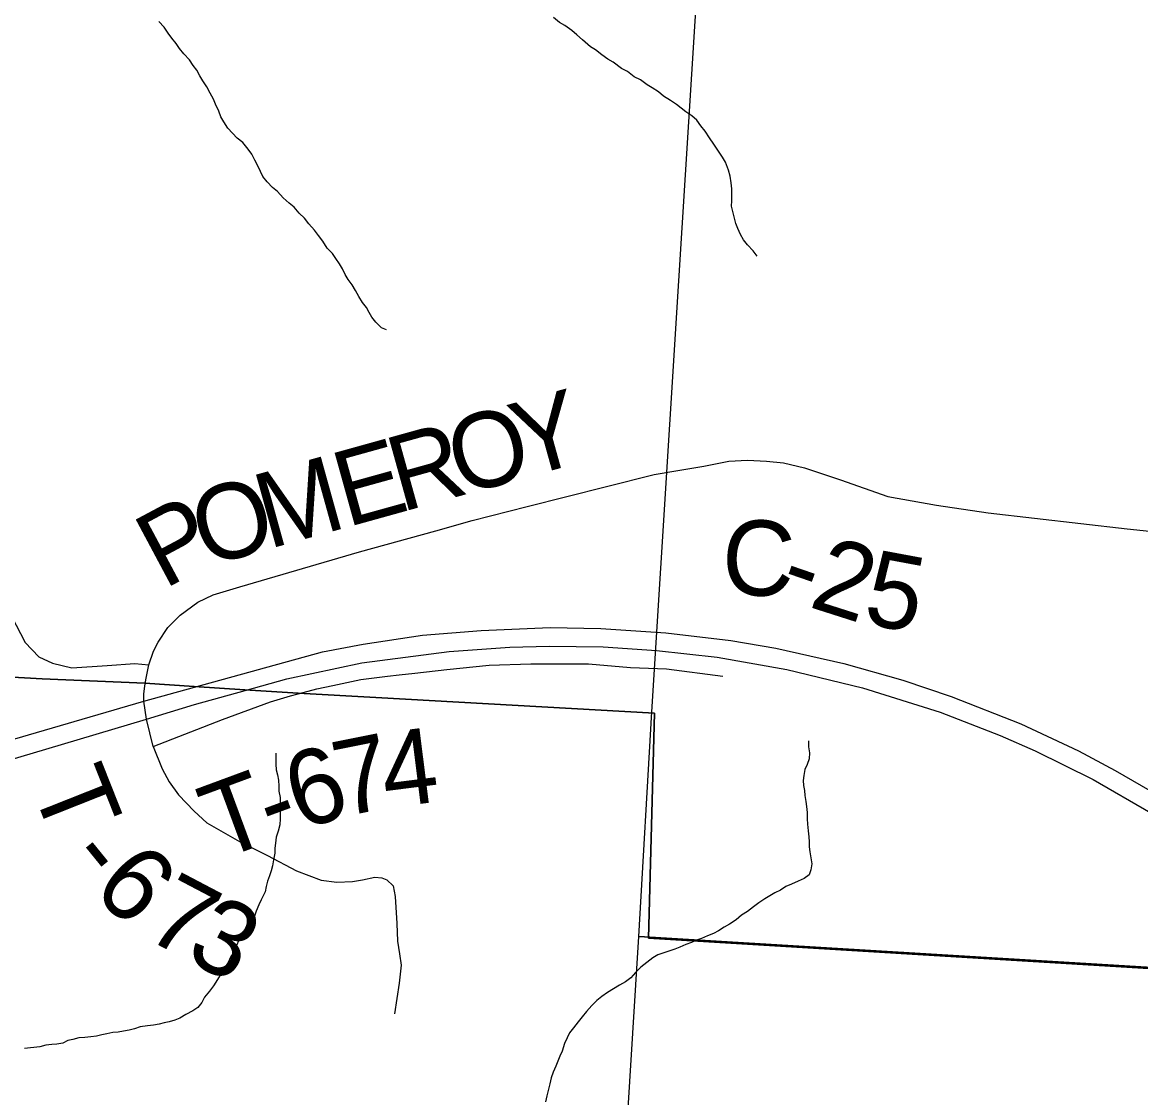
# Model space of a CAD drawing. Extents: x -20.2 to 34, y 0 to 22.
# Drawn here: x 6.324 to 7.17, y 15.823 to 16.636 of the extents above; entities that cross this region are included whole.
import ezdxf

# ---------------------------------------------------------------- set-up
doc = ezdxf.new("R2010")
doc.units = 0
for name, color, linetype in [('Default', 7, 'Continuous'), ('GM_X_County_Road', 7, 'Continuous'), ('GM_X_County_Road_Text', 7, 'Continuous'), ('GM_X_Minor_River', 7, 'Continuous'), ('GM_X_Section', 7, 'Continuous'), ('GM_X_State_Route', 7, 'Continuous'), ('GM_X_Township_Road', 7, 'Continuous'), ('GM_X_Township_Road_Text', 7, 'Continuous'), ('GM_X_US_Route', 7, 'Continuous')]:
    doc.layers.add(name, color=color, linetype=linetype)

msp = doc.modelspace()

# ---------------------------------------------------------------- linework, layer by layer
at = {"layer": 'Default'}
for points in [[(7.35857, 15.90937), (6.79759, 15.94346), (6.80213, 16.11334), (6.59162, 16.12522), (6.53272, 16.12856), (6.49252, 16.13112), (6.45426, 16.13368), (6.41689, 16.13622), (6.33933, 16.13945), (5.77707, 16.17118)], [(5.77707, 16.17118), (6.33933, 16.13945), (6.41689, 16.13622), (6.45426, 16.13368), (6.49252, 16.13112), (6.53272, 16.12856), (6.59162, 16.12522), (6.80213, 16.11334), (6.79759, 15.94346), (7.35857, 15.90937)]]:
    msp.add_lwpolyline(points, dxfattribs=at)
at = {"layer": 'GM_X_County_Road'}
for points in [[(6.63691, 16.25133), (6.66435, 16.25899), (6.70605, 16.26963), (6.76584, 16.28474), (6.80196, 16.29397), (6.81836, 16.2967), (6.83948, 16.30018), (6.85837, 16.30391), (6.87253, 16.30466), (6.88695, 16.30391), (6.89967, 16.30262), (6.91553, 16.29894), (6.94286, 16.28974), (6.97865, 16.27732), (7.01542, 16.27061), (7.05444, 16.26489), (7.15949, 16.25286), (7.23635, 16.24476)], [(6.41615, 16.12258), (6.41621, 16.12812), (6.41677, 16.13388), (6.4171, 16.13569), (6.41789, 16.13993), (6.41989, 16.15005), (6.4235, 16.16027), (6.42697, 16.16705), (6.43436, 16.17814), (6.4435, 16.1875), (6.45697, 16.19725), (6.46861, 16.20282), (6.48882, 16.20899), (6.5793, 16.23532), (6.63691, 16.25133)], [(6.42329, 16.08835), (6.41816, 16.10902), (6.41615, 16.12258)]]:
    msp.add_lwpolyline(points, dxfattribs=at)
at = {"layer": 'GM_X_Minor_River'}
for points in [[(6.87983, 16.45884), (6.87674, 16.46298), (6.87252, 16.46748), (6.86944, 16.47124), (6.86711, 16.47539), (6.86516, 16.47992), (6.8636, 16.4837), (6.86279, 16.48749), (6.86161, 16.49165), (6.86041, 16.49657), (6.86074, 16.50075), (6.86069, 16.50531), (6.86064, 16.50987), (6.8602, 16.51442), (6.85939, 16.51934), (6.8582, 16.52389), (6.85585, 16.52993), (6.85353, 16.5337), (6.85005, 16.53898), (6.84696, 16.5435), (6.84386, 16.54839), (6.84039, 16.55329), (6.83731, 16.55743), (6.83422, 16.56157), (6.83039, 16.56493), (6.8258, 16.56792), (6.8189, 16.57353), (6.81431, 16.57651), (6.80896, 16.57986), (6.80512, 16.58323), (6.80053, 16.58621), (6.79671, 16.58844), (6.79173, 16.59217), (6.78677, 16.59439), (6.78179, 16.59851), (6.77721, 16.60073), (6.77107, 16.60559), (6.76687, 16.60781), (6.76228, 16.61117), (6.75768, 16.61491), (6.75386, 16.61714), (6.74772, 16.62239), (6.74351, 16.62613), (6.73967, 16.6295), (6.73431, 16.63323), (6.73049, 16.63546), (6.72589, 16.6392)], [(6.59958, 16.40329), (6.59576, 16.40476), (6.59154, 16.40889), (6.58846, 16.41265), (6.58652, 16.41642), (6.58458, 16.42019), (6.58149, 16.42395), (6.57879, 16.42848), (6.57608, 16.433), (6.57375, 16.43715), (6.57067, 16.44129), (6.56834, 16.44506), (6.5664, 16.44921), (6.56408, 16.45298), (6.56137, 16.45712), (6.55867, 16.46089), (6.55482, 16.46501), (6.55135, 16.47029), (6.54826, 16.47443), (6.54518, 16.47856), (6.54095, 16.48345), (6.53748, 16.48758), (6.53364, 16.49133), (6.52979, 16.49584), (6.52596, 16.49883), (6.52136, 16.50295), (6.51713, 16.50784), (6.5133, 16.51082), (6.50945, 16.51495), (6.50599, 16.51909), (6.50443, 16.52287), (6.50248, 16.52664), (6.50015, 16.53155), (6.49782, 16.53607), (6.49512, 16.53984), (6.49089, 16.54472), (6.48667, 16.54809), (6.48321, 16.55184), (6.47975, 16.5556), (6.47666, 16.5605), (6.47434, 16.56426), (6.47277, 16.56842), (6.47043, 16.57371), (6.46887, 16.57749), (6.46616, 16.58201), (6.46382, 16.58692), (6.46073, 16.59144), (6.45841, 16.59521), (6.45609, 16.59936), (6.45338, 16.60312), (6.45068, 16.60726), (6.44645, 16.61177), (6.44299, 16.6159), (6.44066, 16.61967), (6.4372, 16.6238), (6.4345, 16.62757), (6.43141, 16.63209), (6.42757, 16.63622)], [(6.91864, 16.09255), (6.91867, 16.08799), (6.91946, 16.08344), (6.91912, 16.07888), (6.91763, 16.07469), (6.91576, 16.07088), (6.91503, 16.06632), (6.91468, 16.06252), (6.91471, 16.05872), (6.91549, 16.05493), (6.9159, 16.05114), (6.91669, 16.04658), (6.9171, 16.04279), (6.91751, 16.03824), (6.91755, 16.03368), (6.91796, 16.0295), (6.91837, 16.02457), (6.91879, 16.02002), (6.91919, 16.01622), (6.91922, 16.01243), (6.91963, 16.00863), (6.92042, 16.00408), (6.92121, 15.99953), (6.92049, 15.99496), (6.919, 15.99116), (6.91522, 15.98847), (6.91068, 15.98654), (6.90576, 15.98423), (6.9016, 15.9823), (6.89744, 15.97961), (6.89327, 15.97768), (6.88949, 15.97537), (6.88571, 15.97307), (6.88118, 15.97), (6.87703, 15.96693), (6.87249, 15.96348), (6.86796, 15.96079), (6.86381, 15.95734), (6.85889, 15.95389), (6.85474, 15.95158), (6.85058, 15.94889), (6.84679, 15.94697), (6.84225, 15.94504), (6.83771, 15.94311), (6.83392, 15.94194), (6.83014, 15.94001), (6.82597, 15.93846), (6.82143, 15.93653), (6.81764, 15.93499), (6.8131, 15.93343), (6.80931, 15.93227), (6.80476, 15.93072), (6.80098, 15.92841), (6.79645, 15.92496), (6.79192, 15.92151), (6.78777, 15.9173), (6.78439, 15.91348), (6.78023, 15.91041), (6.77569, 15.90772), (6.77116, 15.90503), (6.76662, 15.90234), (6.76246, 15.89927), (6.75869, 15.89621), (6.75492, 15.89238), (6.75078, 15.8878), (6.74739, 15.88397), (6.74438, 15.88016), (6.74099, 15.87557), (6.73799, 15.87175), (6.73611, 15.86794), (6.73424, 15.86375), (6.73239, 15.85804), (6.73052, 15.85423), (6.72903, 15.85042), (6.72753, 15.84661), (6.72567, 15.84204), (6.72418, 15.83786), (6.72308, 15.83329), (6.72197, 15.82911), (6.72087, 15.82416), (6.71976, 15.81959)], [(6.51582, 16.08321), (6.51585, 16.07941), (6.51589, 16.07485), (6.51629, 16.07068), (6.51708, 16.06689), (6.51787, 16.06272), (6.51828, 16.05816), (6.51831, 16.05436), (6.5191, 16.04981), (6.51913, 16.04602), (6.51917, 16.04108), (6.5192, 16.03728), (6.51922, 16.03349), (6.51888, 16.02893), (6.51777, 16.02436), (6.51629, 16.01979), (6.51556, 16.01523), (6.51521, 16.01143), (6.51524, 16.00764), (6.51413, 16.00269), (6.51341, 15.99813), (6.51229, 15.99432), (6.51118, 15.99052), (6.5097, 15.98633), (6.50858, 15.98252), (6.50785, 15.97834), (6.50486, 15.97224), (6.50299, 15.96843), (6.50113, 15.96386), (6.49964, 15.95929), (6.49664, 15.95433), (6.49364, 15.94938), (6.49063, 15.94556), (6.488, 15.94174), (6.48613, 15.93793), (6.48464, 15.93336), (6.48201, 15.92955), (6.47977, 15.92497), (6.47676, 15.92039), (6.47451, 15.91658), (6.47189, 15.912), (6.46888, 15.90743), (6.46588, 15.90323), (6.46211, 15.89864), (6.45986, 15.89483), (6.45685, 15.89101), (6.45307, 15.88832), (6.44778, 15.88563), (6.44324, 15.88293), (6.43946, 15.88139), (6.43529, 15.88022), (6.43149, 15.87943), (6.42771, 15.87827), (6.42353, 15.87748), (6.41898, 15.87707), (6.41329, 15.87626), (6.40913, 15.87472), (6.40496, 15.87393), (6.40078, 15.87314), (6.39661, 15.87235), (6.39282, 15.87194), (6.38827, 15.87115), (6.38448, 15.87036), (6.38031, 15.86919), (6.37614, 15.86878), (6.37158, 15.86837), (6.36703, 15.86796), (6.36248, 15.86679), (6.35869, 15.866), (6.35491, 15.86407), (6.35035, 15.86328), (6.34656, 15.86287), (6.342, 15.86246), (6.33746, 15.86129), (6.32585, 15.86007)]]:
    msp.add_lwpolyline(points, dxfattribs=at)
at = {"layer": 'GM_X_Section'}
for points in [[(6.85272, 16.95336), (7.92004, 16.89751), (7.86237, 15.87982), (6.79044, 15.94473), (6.80008, 16.11433), (6.82053, 16.44033)], [(6.79044, 15.94473), (7.86237, 15.87982), (7.79854, 14.87534), (6.72741, 14.93458), (6.77473, 15.69297)]]:
    msp.add_lwpolyline(points, close=True, dxfattribs=at)
at = {"layer": 'GM_X_State_Route'}
for points in [[(6.41816, 16.10902), (6.45434, 16.11988), (6.49273, 16.13059), (6.52435, 16.13942), (6.58094, 16.15154), (6.6469, 16.16005), (6.69286, 16.16322), (6.72265, 16.1641), (6.76329, 16.16346), (6.80371, 16.16069), (6.84945, 16.1558), (6.90222, 16.14644), (6.95945, 16.13261), (7.01817, 16.11431), (7.06349, 16.09644), (7.08985, 16.08496), (7.1337, 16.06325), (7.17753, 16.03814), (7.32636, 15.9492)], [(5.70798, 16.00059), (5.75952, 15.99571), (5.78079, 15.9937), (5.8229, 15.9917), (5.87097, 15.99099), (5.90512, 15.99177), (5.95501, 15.99474), (6.02628, 16.00299), (6.07084, 16.0112), (6.10003, 16.01721), (6.16012, 16.03272), (6.18755, 16.04048), (6.34217, 16.08621), (6.41816, 16.10902)]]:
    msp.add_lwpolyline(points, dxfattribs=at)
at = {"layer": 'GM_X_Township_Road'}
for points in [[(6.31618, 16.18671), (6.32646, 16.16685), (6.33674, 16.15612), (6.34702, 16.15121)], [(6.34702, 16.15121), (6.36177, 16.14764), (6.3884, 16.14941), (6.40925, 16.1509), (6.41989, 16.15005)], [(6.60925, 16.14233), (6.621, 16.14361), (6.6452, 16.14644), (6.67711, 16.14963), (6.7086, 16.15069), (6.75222, 16.15069), (6.78415, 16.14808), (6.81137, 16.14687), (6.85387, 16.14138)], [(6.55898, 16.13431), (6.5801, 16.13878), (6.60044, 16.14138), (6.60925, 16.14233)], [(6.42329, 16.08835), (6.47563, 16.10856), (6.51201, 16.12197), (6.5269, 16.12643), (6.53293, 16.12804), (6.54691, 16.13175), (6.55898, 16.13431)], [(6.42329, 16.08835), (6.4301, 16.07133), (6.43523, 16.06156), (6.44222, 16.05176), (6.4541, 16.03944), (6.46382, 16.03046), (6.48846, 16.01638), (6.50952, 16.00575), (6.53146, 15.99422), (6.5503, 15.98712), (6.56205, 15.98579), (6.5738, 15.98624), (6.58134, 15.98757), (6.59087, 15.98957), (6.59596, 15.9889), (6.59973, 15.98757), (6.60461, 15.98292), (6.60616, 15.97493), (6.60749, 15.95432), (6.60794, 15.94102), (6.60948, 15.93149), (6.6106, 15.92284), (6.60904, 15.90932), (6.60572, 15.88627)]]:
    msp.add_lwpolyline(points, dxfattribs=at)
at = {"layer": 'GM_X_US_Route'}
for points in [[(6.41615, 16.12258), (6.45447, 16.13315), (6.55116, 16.15984), (6.58201, 16.16559), (6.62691, 16.17239), (6.67116, 16.17601), (6.72329, 16.17814), (6.76158, 16.1775), (6.81073, 16.17409), (6.85988, 16.16835), (6.89392, 16.1626), (6.94541, 16.1509), (6.98987, 16.13835), (7.02647, 16.12601), (7.07902, 16.10538), (7.12264, 16.08495), (7.15051, 16.07006), (7.19455, 16.04453), (7.23689, 16.01878), (7.33754, 15.95848)], [(6.41816, 16.10902), (6.45434, 16.11988), (6.49273, 16.13059), (6.52435, 16.13942), (6.58094, 16.15154), (6.6469, 16.16005), (6.69286, 16.16322), (6.72265, 16.1641), (6.76329, 16.16346), (6.80371, 16.16069), (6.84945, 16.1558), (6.90222, 16.14644), (6.95945, 16.13261), (7.01817, 16.11431), (7.06349, 16.09644), (7.08985, 16.08496), (7.1337, 16.06325), (7.17753, 16.03814), (7.32636, 15.9492)], [(5.57956, 16.02628), (5.70988, 16.01439), (5.76077, 16.00973), (5.81569, 16.00576), (5.83769, 16.00491), (5.86626, 16.00491), (5.88769, 16.00519), (5.90798, 16.00576), (5.93398, 16.00748), (5.94484, 16.00834), (5.95884, 16.00977), (5.97656, 16.01148), (6.00313, 16.01463), (6.03856, 16.01976), (6.0657, 16.02462), (6.0937, 16.03091), (6.1337, 16.04005), (6.41615, 16.12258)], [(5.70798, 16.00059), (5.75952, 15.99571), (5.78079, 15.9937), (5.8229, 15.9917), (5.87097, 15.99099), (5.90512, 15.99177), (5.95501, 15.99474), (6.02628, 16.00299), (6.07084, 16.0112), (6.10003, 16.01721), (6.16012, 16.03272), (6.18755, 16.04048), (6.34217, 16.08621), (6.41816, 16.10902)]]:
    msp.add_lwpolyline(points, dxfattribs=at)

# ---------------------------------------------------------------- texts
at = {"layer": 'GM_X_County_Road_Text'}
for s, rotation, p in [('Y', 15.55718, (6.70371, 16.29105)), ('O', 15.51455, (6.65548, 16.27767)), ('R', 15.52347, (6.61052, 16.26518)), ('E', 15.5186, (6.56957, 16.25381)), ('M', 15.52142, (6.51015, 16.23731)), ('O', 15.92288, (6.46217, 16.22362)), ('P', 28.11636, (6.43132, 16.20675)), ('C', 356.87993, (6.85184, 16.2039)), ('2', 342.30026, (6.91775, 16.19413)), ('5', 349.446, (6.95859, 16.1816)), ('-', 341.02198, (6.89437, 16.20216))]:
    msp.add_text(s, height=0.05682, rotation=rotation, dxfattribs=at).set_placement(p)
at = {"layer": 'GM_X_Township_Road_Text'}
for s, rotation, p in [('7', 11.33545, (6.56589, 16.0349)), ('4', 7.16374, (6.59912, 16.0416)), ('6', 17.98238, (6.53428, 16.02453)), ('T', 291.63351, (6.33054, 16.05837)), ('T', 20.27967, (6.47307, 16.00197)), ('-', 20.12849, (6.5129, 16.01668)), ('-', 309.10922, (6.35573, 16.00263)), ('6', 316.18812, (6.37563, 15.9789)), ('7', 332.27186, (6.41495, 15.94454)), ('3', 332.12924, (6.4459, 15.92827))]:
    msp.add_text(s, height=0.05682, rotation=rotation, dxfattribs=at).set_placement(p)

doc.saveas('drawing.dxf')
